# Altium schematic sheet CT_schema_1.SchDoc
size 551 x 495 mm
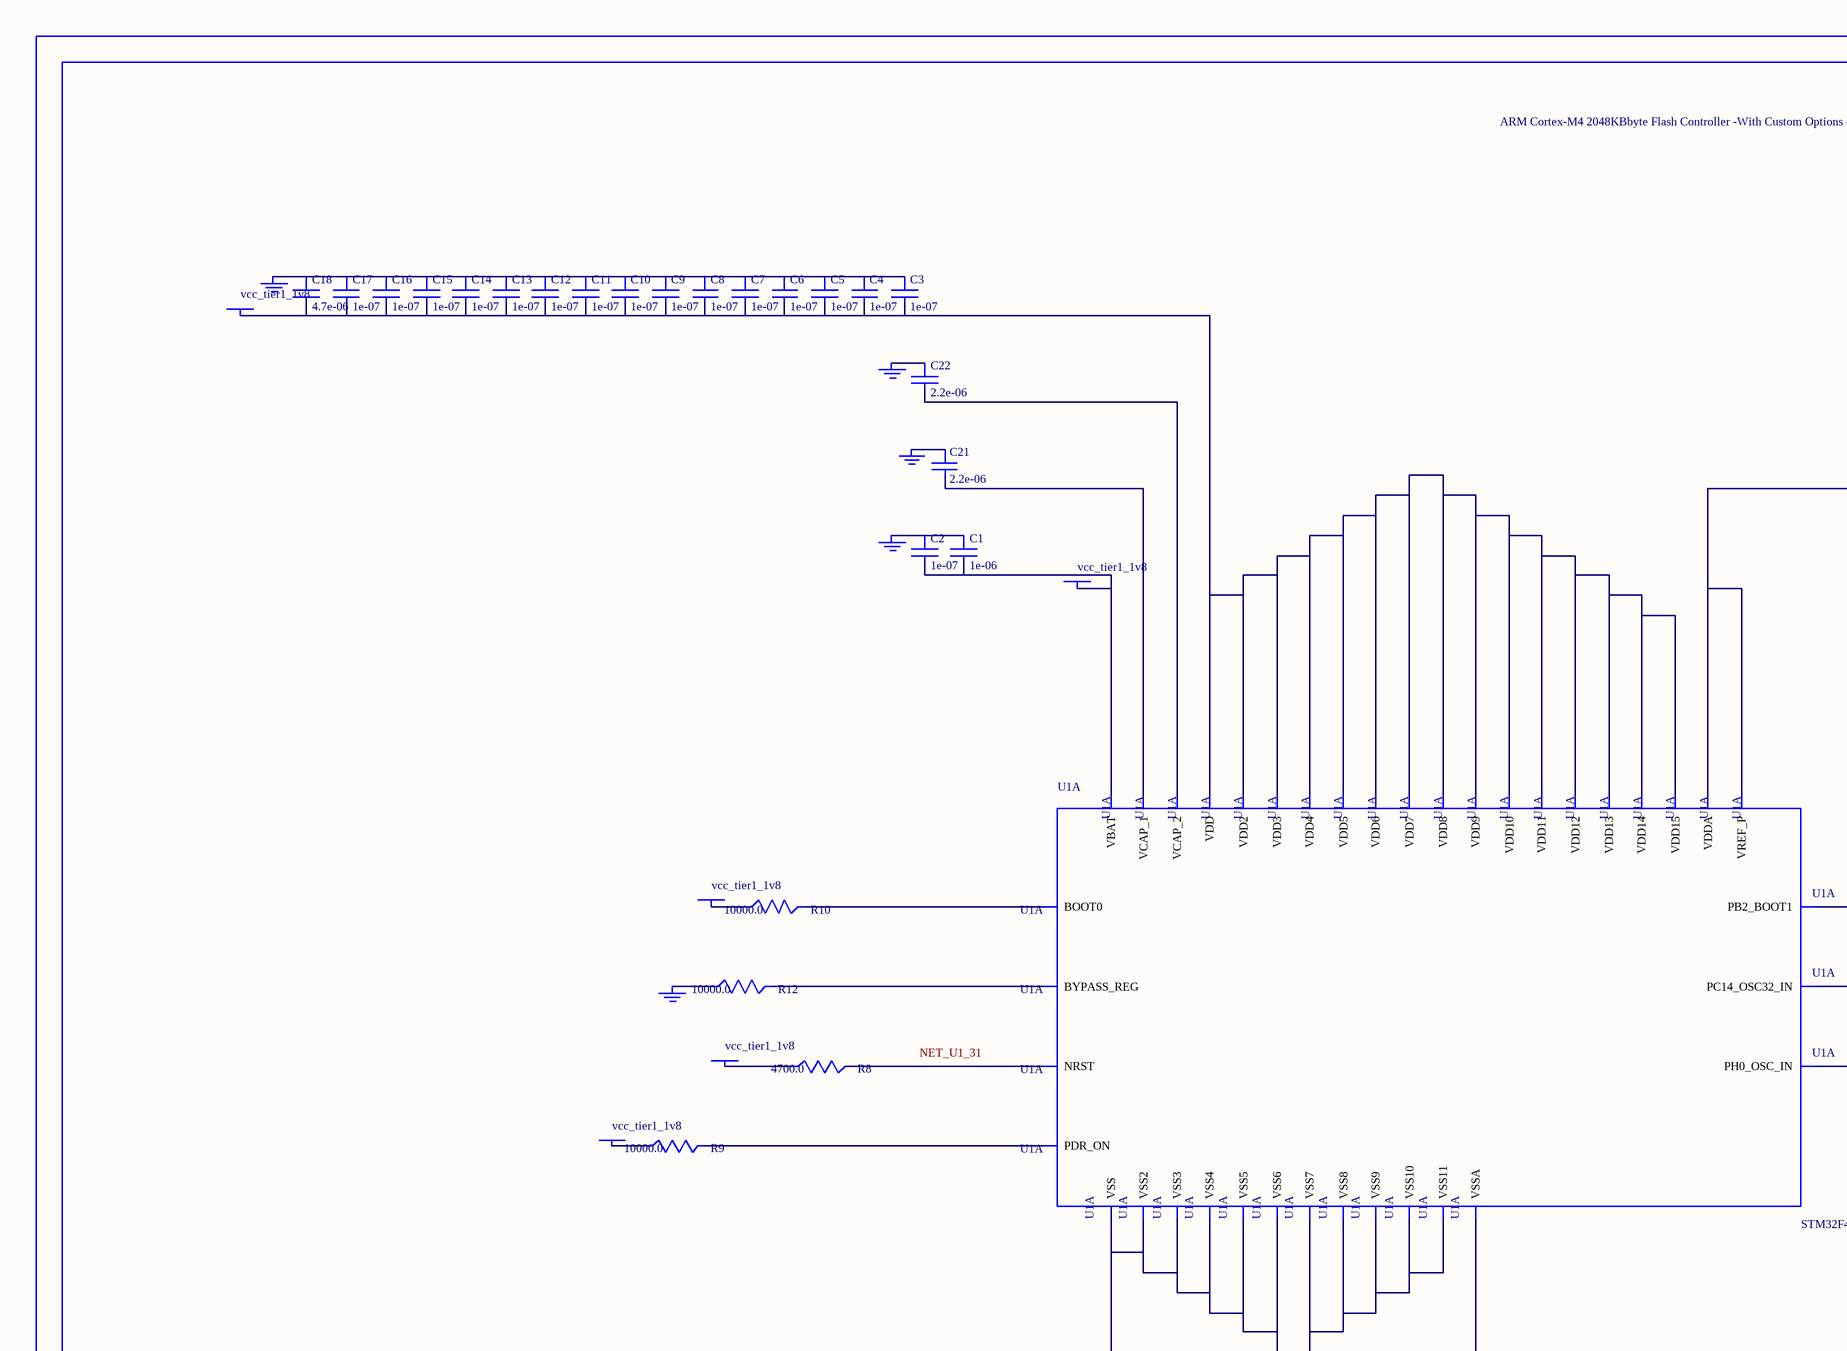
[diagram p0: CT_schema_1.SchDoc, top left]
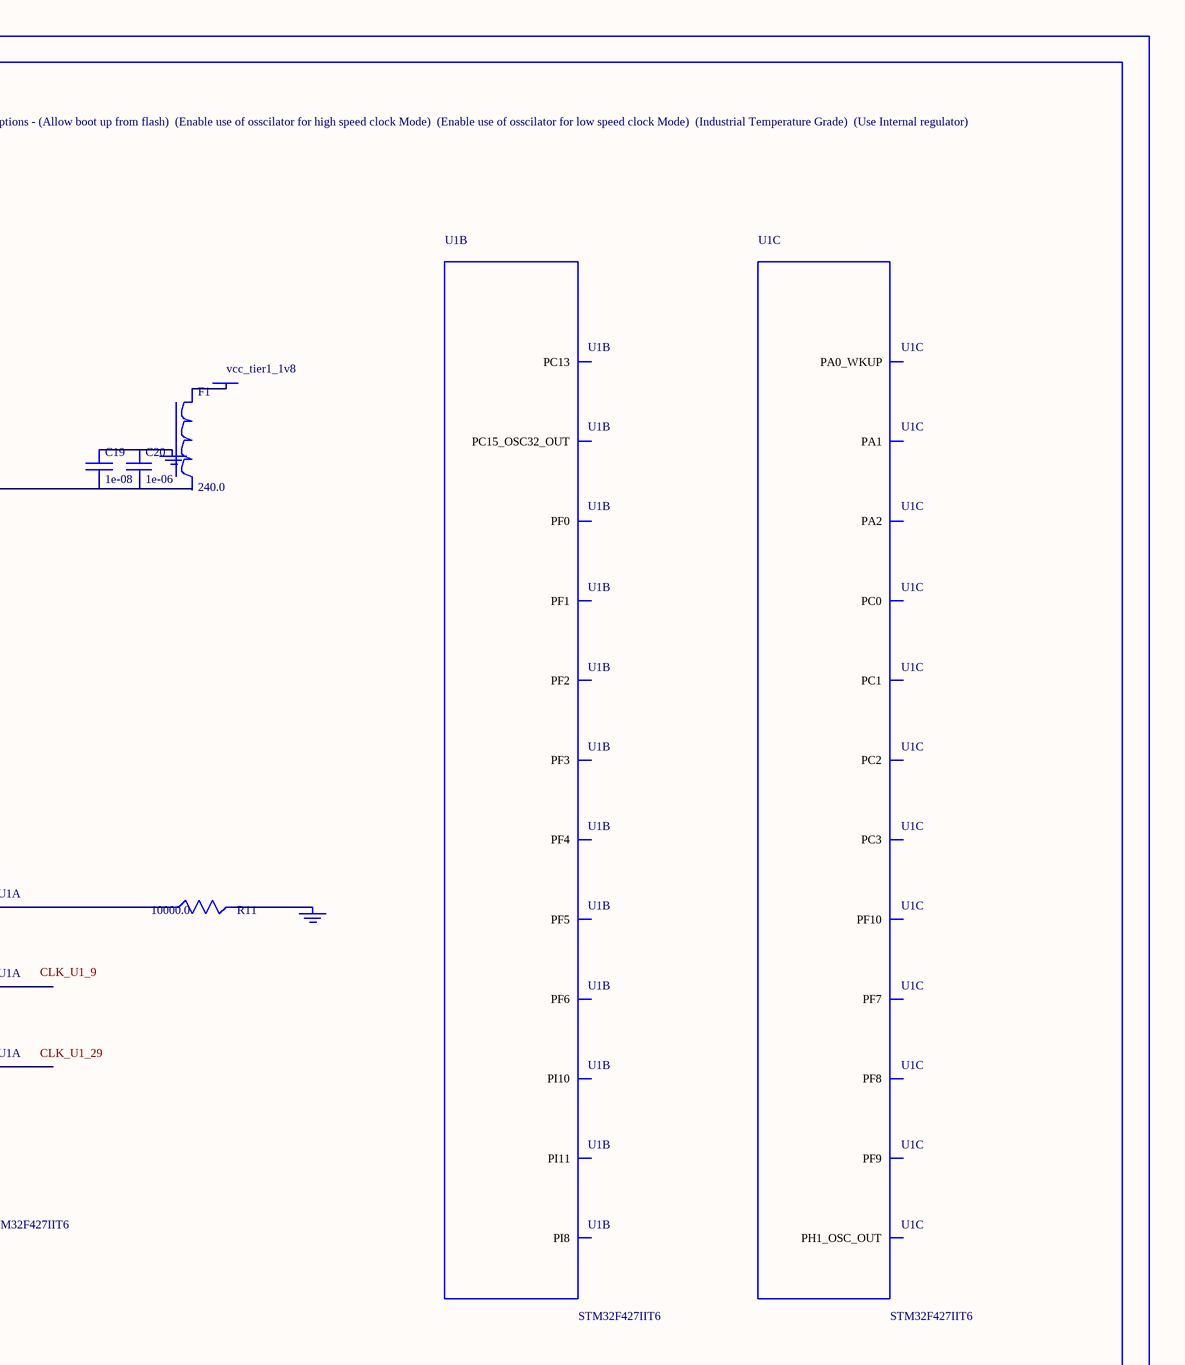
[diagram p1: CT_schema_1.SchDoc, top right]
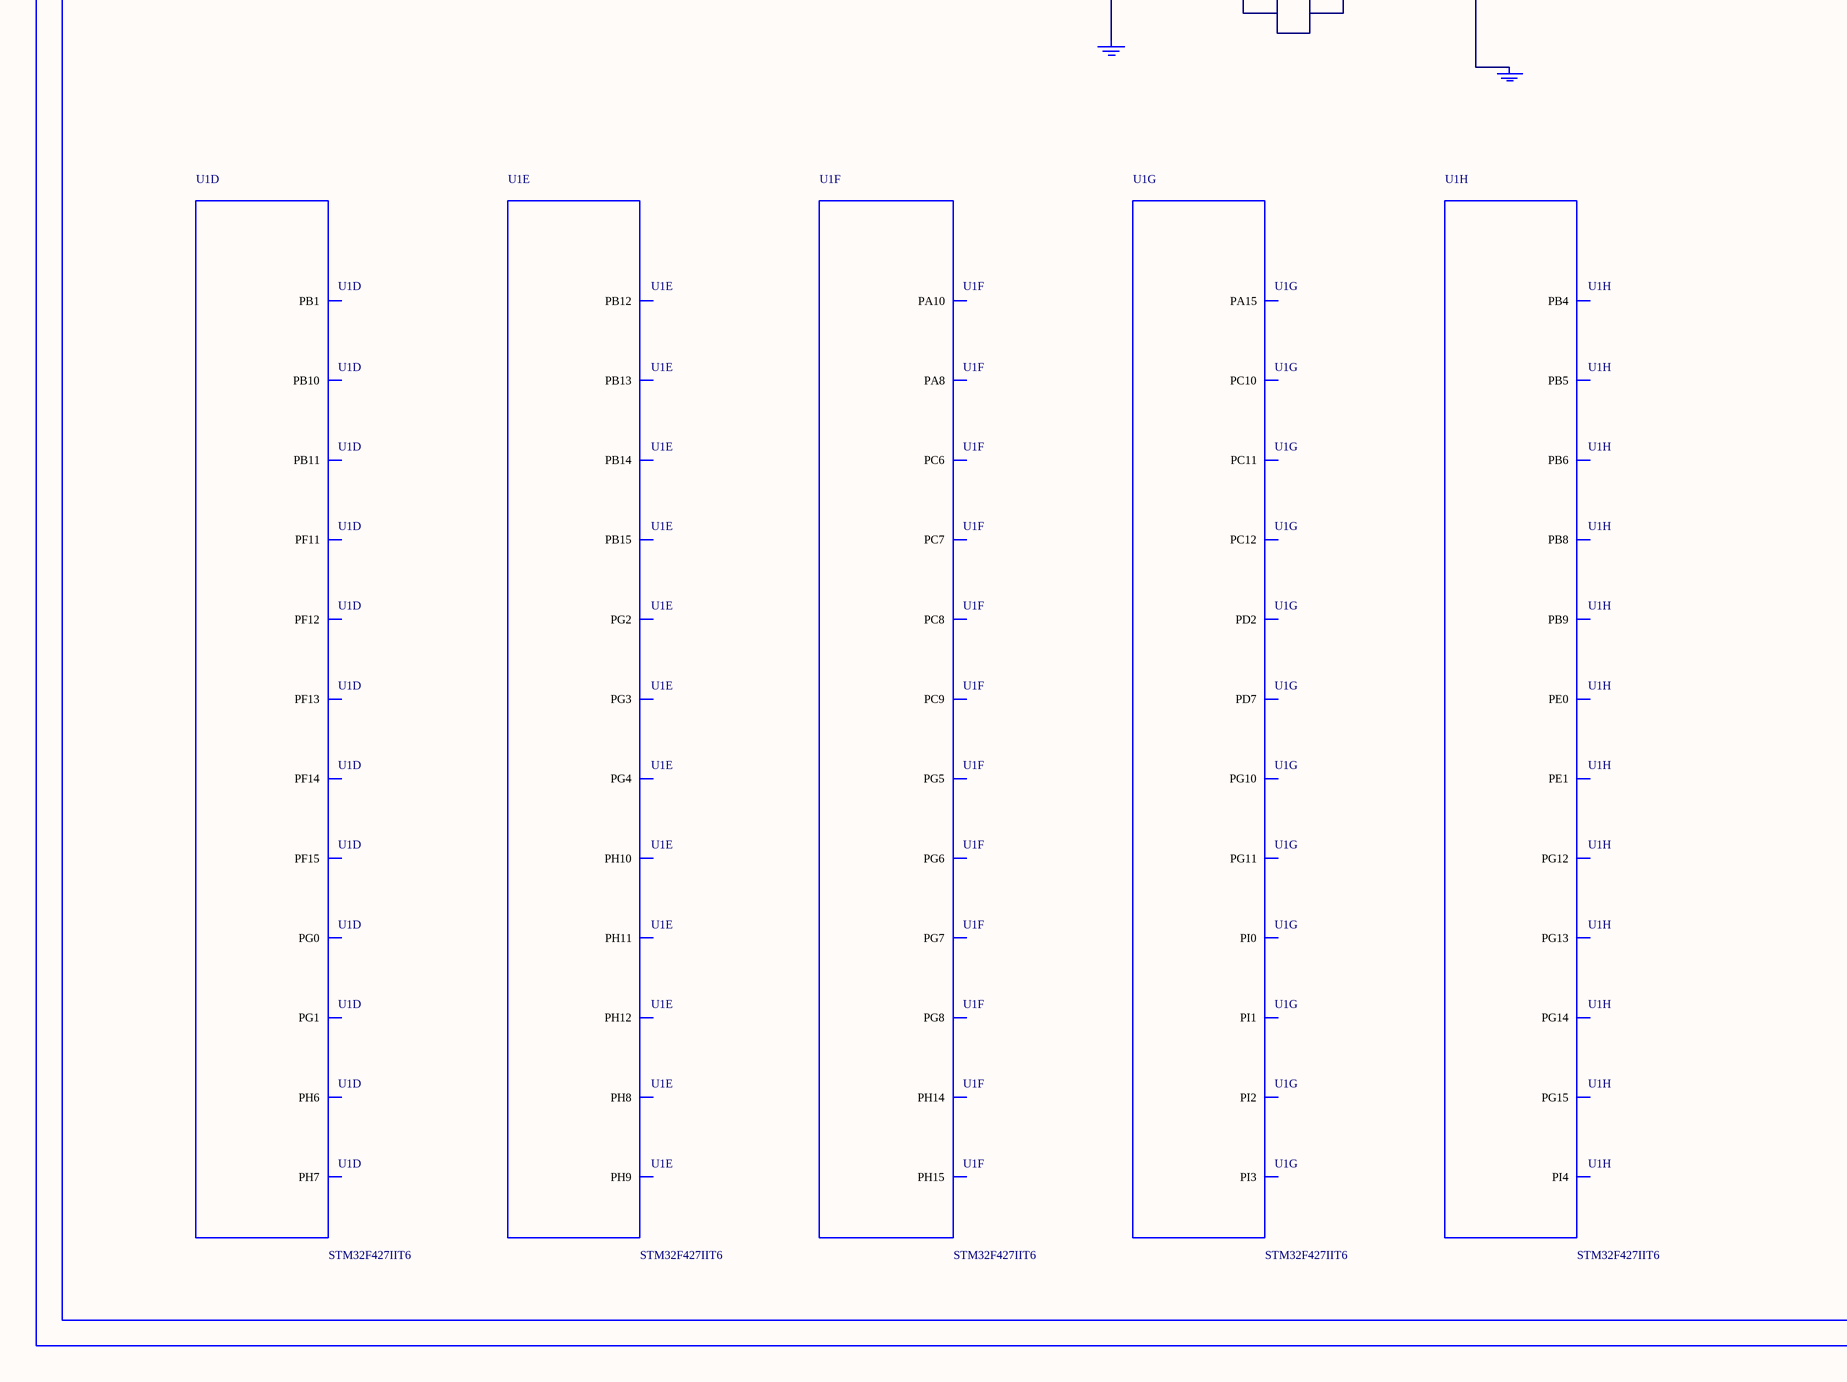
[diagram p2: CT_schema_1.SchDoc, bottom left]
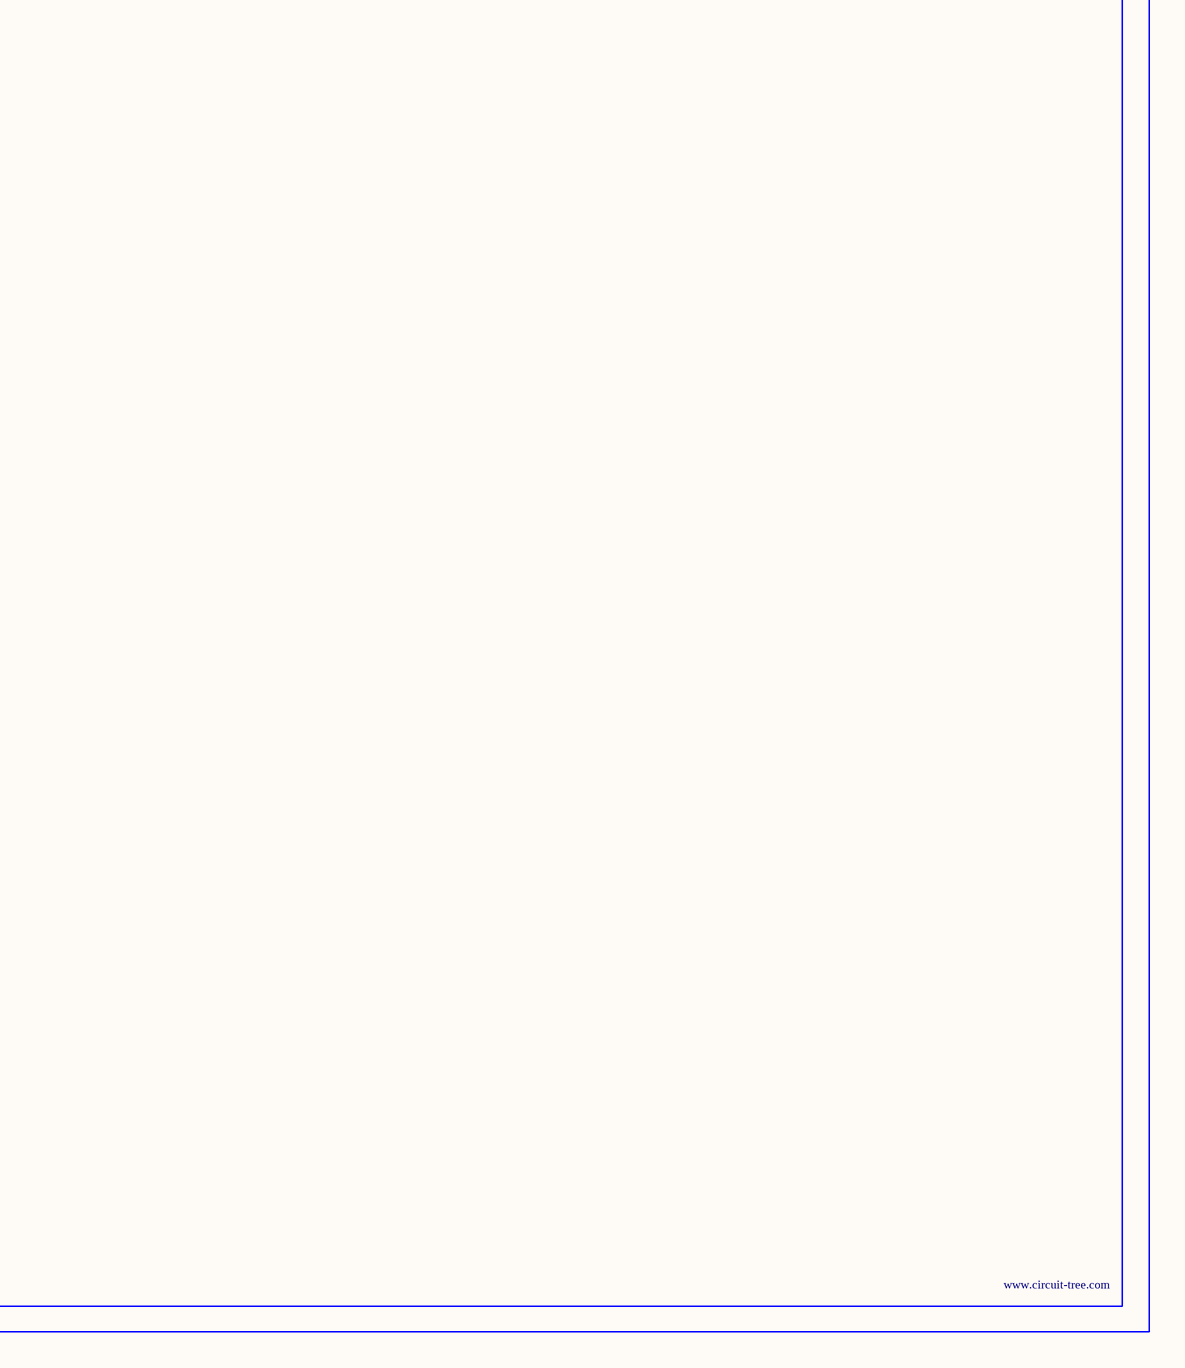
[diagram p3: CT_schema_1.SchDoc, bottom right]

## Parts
BORDER0  (no value)
C1  1e-06  [C0603]
C2  1e-07  [C0603]
C3  1e-07  [C0603]
C4  1e-07  [C0603]
C5  1e-07  [C0603]
C6  1e-07  [C0603]
C7  1e-07  [C0603]
C8  1e-07  [C0603]
C9  1e-07  [C0603]
C10  1e-07  [C0603]
C11  1e-07  [C0603]
C12  1e-07  [C0603]
C13  1e-07  [C0603]
C14  1e-07  [C0603]
C15  1e-07  [C0603]
C16  1e-07  [C0603]
C17  1e-07  [C0603]
C18  4.7e-06  [C0603]
C19  1e-08  [C0603]
C20  1e-06  [C0603]
C21  2.2e-06  [C0603]
C22  2.2e-06  [C0603]
F1  240.0  [L0603]
GND_INSTANCE_0_0  (no value)
GND_INSTANCE_0_1  (no value)
GND_INSTANCE_0_2  (no value)
GND_INSTANCE_0_3  (no value)
GND_INSTANCE_0_4  (no value)
GND_INSTANCE_0_5  (no value)
GND_INSTANCE_0_6  (no value)
GND_INSTANCE_0_7  (no value)
GND_INSTANCE_0_8  (no value)
POWER_INSTANCE_0_0  vcc_tier1_1v8
POWER_INSTANCE_0_1  vcc_tier1_1v8
POWER_INSTANCE_0_2  vcc_tier1_1v8
POWER_INSTANCE_0_3  vcc_tier1_1v8
POWER_INSTANCE_0_4  vcc_tier1_1v8
POWER_INSTANCE_0_5  vcc_tier1_1v8
R8  4700.0  [R0603]
R9  10000.0  [R0603]
R10  10000.0  [R0603]
R11  10000.0  [R0603]
R12  10000.0  [R0603]
U1  STM32F427IIT6  [LQFP176]  (parts A,B,C,D,E,F,G,H of 14)

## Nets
NetC1_1: C1.1 C2.1 GND_INSTANCE_0_0.0(GND)
NetC1_2: C1.2 C2.2 POWER_INSTANCE_0_0.0(PWR) U1.6(VBAT)
NetC3_1: C3.1 C4.1 C5.1 C6.1 C7.1 C8.1 C9.1 C10.1 C11.1 C12.1 C13.1 C14.1 C15.1 C16.1 C17.1 C18.1 GND_INSTANCE_0_1.0(GND)
NetC3_2: C3.2 C4.2 C5.2 C6.2 C7.2 C8.2 C9.2 C10.2 C11.2 C12.2 C13.2 C14.2 C15.2 C16.2 C17.2 C18.2 POWER_INSTANCE_0_1.0(PWR) U1.15(VDD) U1.23(VDD2) U1.36(VDD3) U1.49(VDD4) U1.62(VDD5) U1.72(VDD6) U1.82(VDD7) U1.91(VDD8) U1.103(VDD9) U1.114(VDD10) U1.127(VDD11) U1.136(VDD12) U1.149(VDD13) U1.159(VDD14) U1.172(VDD15)
NetC19_1: C19.1 C20.1 GND_INSTANCE_0_3.0(GND)
NetC19_2: C19.2 C20.2 U1.38(VREF_P) U1.39(VDDA)
NetC21_1: C21.1 GND_INSTANCE_0_6.0(GND)
NetC21_2: C21.2 U1.81(VCAP_1)
NetC22_1: C22.1 GND_INSTANCE_0_7.0(GND)
NetC22_2: C22.2 U1.125(VCAP_2)
NetF1_1: F1.1 POWER_INSTANCE_0_2.0(PWR)
NetGND_INSTANCE_0_2_0: GND_INSTANCE_0_2.0(GND) U1.37(VSSA)
NetGND_INSTANCE_0_4_0: GND_INSTANCE_0_4.0(GND) R12.1
NetGND_INSTANCE_0_5_0: GND_INSTANCE_0_5.0(GND) R11.2
NetGND_INSTANCE_0_8_0: GND_INSTANCE_0_8.0(GND) U1.14(VSS) U1.22(VSS2) U1.61(VSS3) U1.71(VSS4) U1.90(VSS5) U1.102(VSS6) U1.113(VSS7) U1.126(VSS8) U1.135(VSS9) U1.148(VSS10) U1.158(VSS11)
NetPOWER_INSTANCE_0_3_0: POWER_INSTANCE_0_3.0(PWR) R10.1
NetPOWER_INSTANCE_0_4_0: POWER_INSTANCE_0_4.0(PWR) R9.1
NetPOWER_INSTANCE_0_5_0: POWER_INSTANCE_0_5.0(PWR) R8.1
NetR8_2: R8.2 U1.31(NRST)
NetR9_2: R9.2 U1.171(PDR_ON)
NetR10_2: R10.2 U1.166(BOOT0)
NetR11_1: R11.1 U1.58(PB2_BOOT1)
NetR12_2: R12.2 U1.48(BYPASS_REG)

Not connected (* = marked no-connect by the designer): F1 2; U1 7(PI8) 8(PC13) 9(PC14_OSC32_IN) 10(PC15_OSC32_OUT) 12(PI10) 13(PI11) 16(PF0) 17(PF1) 18(PF2) 19(PF3) 20(PF4) 21(PF5) 24(PF6) 25(PF7) 26(PF8) 27(PF9) 28(PF10) 29(PH0_OSC_IN) 30(PH1_OSC_OUT) 32(PC0) 33(PC1) 34(PC2) 35(PC3) 40(PA0_WKUP) 41(PA1) 42(PA2) 57(PB1) 59(PF11) 60(PF12) 63(PF13) 64(PF14) 65(PF15) 66(PG0) 67(PG1) 79(PB10) 80(PB11) 83(PH6) 84(PH7) 85(PH8) 86(PH9) 87(PH10) 88(PH11) 89(PH12) 92(PB12) 93(PB13) 94(PB14) 95(PB15) 106(PG2) 107(PG3) 108(PG4) 109(PG5) 110(PG6) 111(PG7) 112(PG8) 115(PC6) 116(PC7) 117(PC8) 118(PC9) 119(PA8) 121(PA10) 129(PH14) 130(PH15) 131(PI0) 132(PI1) 133(PI2) 134(PI3) 138(PA15) 139(PC10) 140(PC11) 141(PC12) 144(PD2) 151(PD7) 153(PG10) 154(PG11) 155(PG12) 156(PG13) 157(PG14) 160(PG15) 162(PB4) 163(PB5) 164(PB6) 167(PB8) 168(PB9) 169(PE0) 170(PE1) 173(PI4)

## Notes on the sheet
- Labels drawn without touching a wire or pin: CLK_U1_9, CLK_U1_29, NET_U1_31

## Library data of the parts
BORDER0 = BORDER_PAGE0
C1 C20 = C0603C105K3RACTU
C2-C17 = 06035C104K4Z2A
C18 = GRM188R6YA475KE15D
C19 = 06035C103K4Z2A
C21 C22 = C0603C225K8RACTU
F1 = Z0603C241ASMST
GND_INSTANCE_0_0-GND_INSTANCE_0_8 = GND
POWER_INSTANCE_0_0-POWER_INSTANCE_0_5 = PWR
R8 = RC0603JR-074K7L
R9-R12 = RC0603JR-0710KL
